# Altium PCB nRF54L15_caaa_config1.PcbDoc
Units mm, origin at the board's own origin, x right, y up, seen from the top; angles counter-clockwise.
Board outline 10.87 x 8.27 mm, 8 copper layers (Top Layer, Mid-Layer 1, Mid-Layer 2, Mid-Layer 3, Mid-Layer 4, Mid-Layer 5, Mid-Layer 6, Bottom Layer), stack 1.547 mm thick; 19 components, 47 nets, 85 pads, 110 vias.
Unrouted connection lines stored in the file: 18.
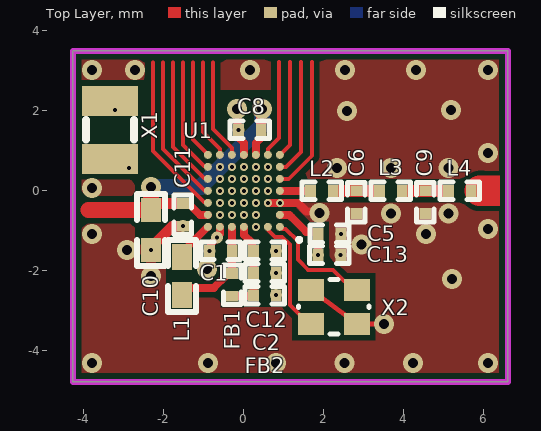
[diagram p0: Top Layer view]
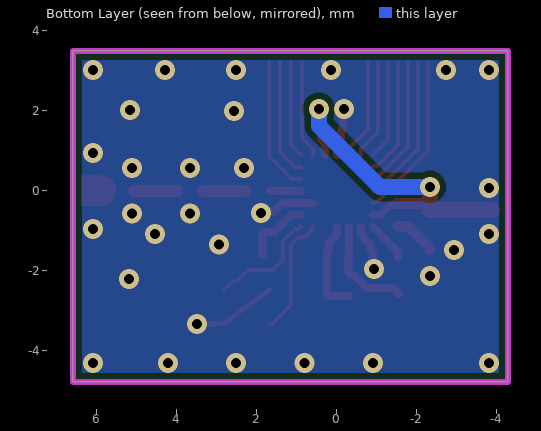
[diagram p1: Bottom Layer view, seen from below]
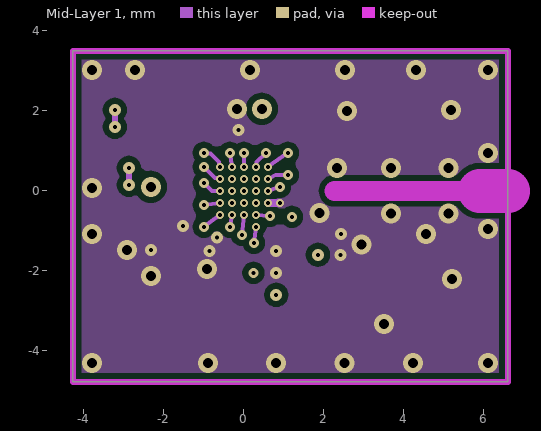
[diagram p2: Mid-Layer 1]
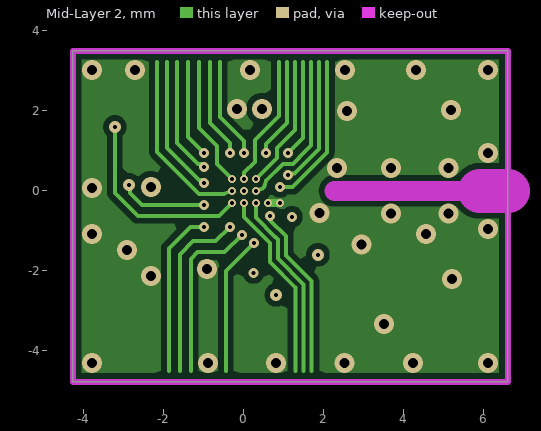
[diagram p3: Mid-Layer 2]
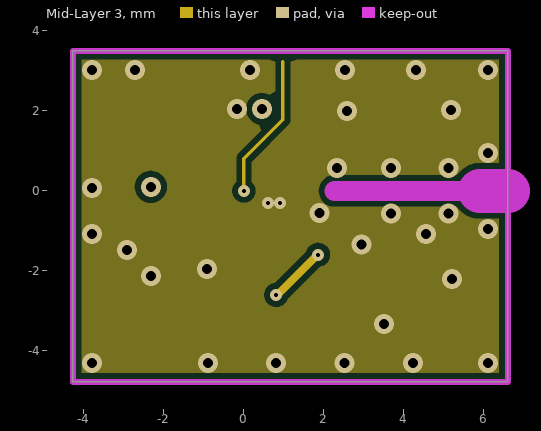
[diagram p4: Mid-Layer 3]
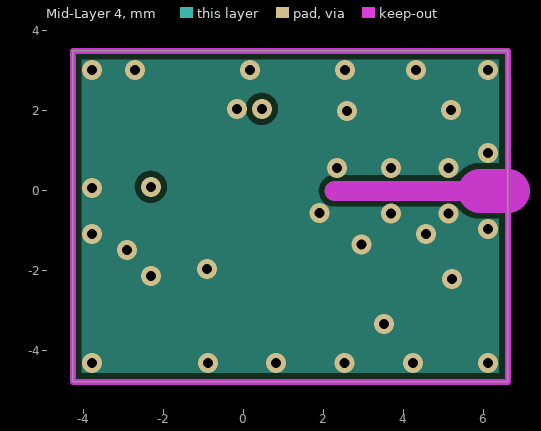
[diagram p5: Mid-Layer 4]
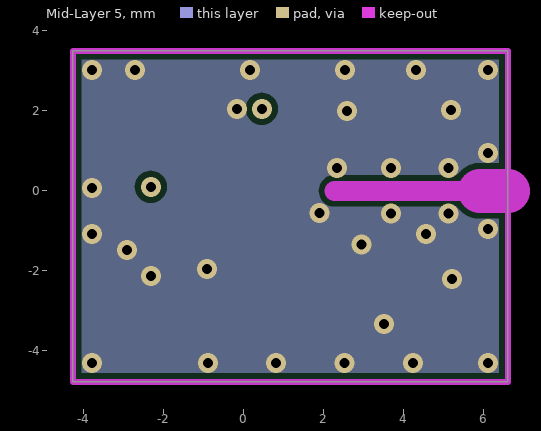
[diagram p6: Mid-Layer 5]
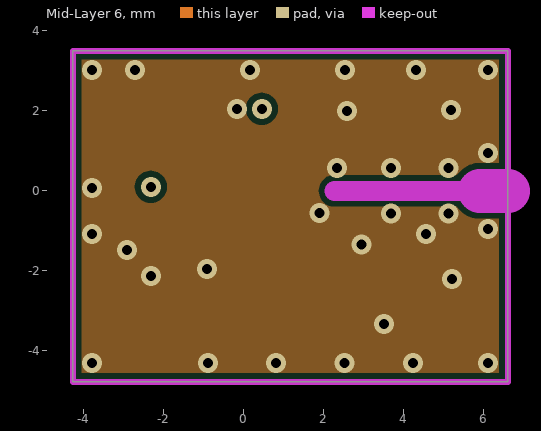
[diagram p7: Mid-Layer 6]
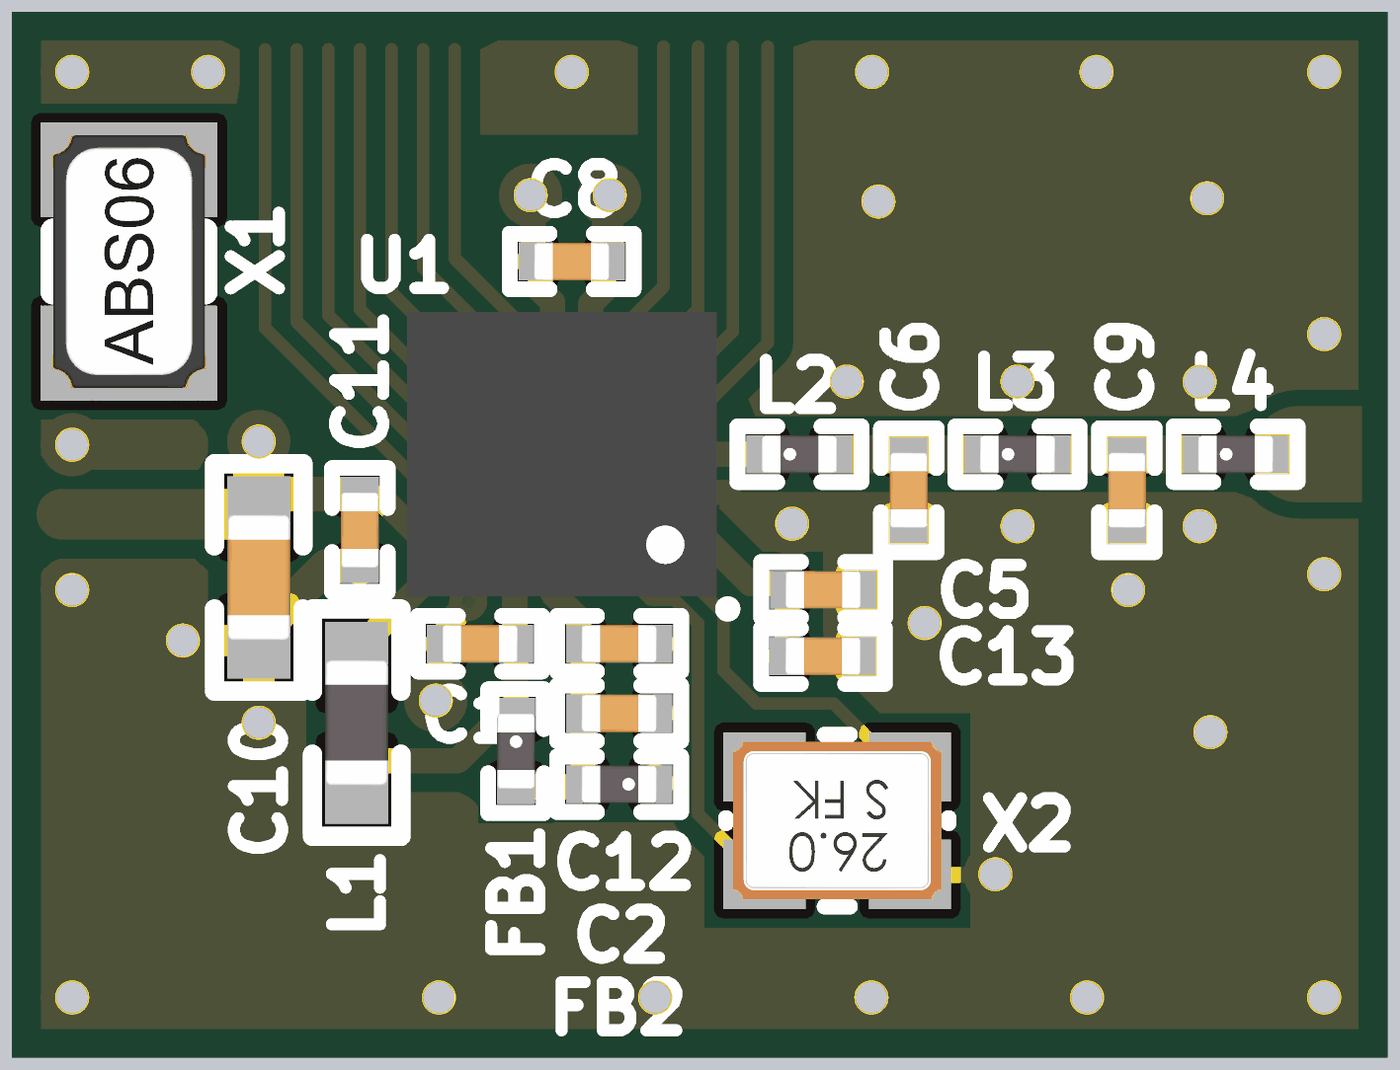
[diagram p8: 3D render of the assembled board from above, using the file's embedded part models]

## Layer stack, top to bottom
Top Solder: solder mask 0.011, Solder Resist, Dk 3.5
Top Layer: signal copper 0.035
Dielectric 1: prepreg 0.08, Dk 4.2
Mid-Layer 1: signal copper 0.035
Dielectric 2: prepreg 0.08, Dk 4.1
Mid-Layer 2: signal copper 0.035
Dielectric 6: prepreg 0.08, Dk 4.1
Mid-Layer 3: signal copper 0.035
Dielectric 3: core 0.7874, Dk 4.6
Mid-Layer 4: signal copper 0.035
Dielectric 7: prepreg 0.08, Dk 4.1
Mid-Layer 5: signal copper 0.035
Dielectric 4: prepreg 0.08, Dk 4.1
Mid-Layer 6: signal copper 0.035
Dielectric 5: prepreg 0.08, Dk 4.2
Bottom Layer: signal copper 0.035
Board Layer Stack Bottom Solder: solder mask 0.011, Solder Resist, Dk 3.5

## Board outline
-4.275,-4.775 6.6,-4.775 6.6,3.5 -4.275,3.5

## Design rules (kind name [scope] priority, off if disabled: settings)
Clearance Polygon_ANT [(InNamedPolygon('GND')) or (InNamedPolygon('Bottom_Layer-GND')) or IsRegion vs InNet('RF')] p1: gap=0.127 ignorepadtopadclearanceinfootprint=FALSE
Clearance Clearance_Poly [IsRegion] p2: gap=0.15 ignorepadtopadclearanceinfootprint=FALSE
Clearance [All] p3: gap=0.1 ignorepadtopadclearanceinfootprint=FALSE
ComponentClearance [All] p1 off: gap=0.254 collisioncheckmode=3 verticalgap=0.254 showdistances=FALSE
FabricationTestPointUsage TestPointUsage [All] p1: valid=0 allowmultiple=FALSE
FabricationTestpoint Testpoint [All] p1: side=3 testpointundercomponent=TRUE minsize=1.016 maxsize=2.54 preferedsize=1.524 minholesize=0 maxholesize=1.016 preferedholesize=0.813 testpointgrid=0.025 allowsidetop=TRUE allowsidebottom=TRUE usegrid=TRUE gridtolerance=0
Height [All] p1 off: minheight=0 maxheight=25.4 prefheight=12.7
HoleSize [All] p1: absolutevalues=TRUE maxlimit=4 minlimit=0.1 maxpercent=80.000 minpercent=20.000
HoleToHoleClearance [IsThruVia vs IsThruVia] p1: gap=0.36 allowstackedmicrovias=TRUE
MinimumAnnularRing [All] p1 off: minimumring=0.152
PlaneClearance [All] p1: clearance=0.2
PolygonConnect "Direct Connect" [isVia and innet(gnd) or InComponent('C6') or InComponent('C9') or InComponent('C3') or  InComponent('C5') or InComponent('C13')] p1: connectstyle=Direct reliefconductorwidth=0.254 reliefentries=4 polygonreliefangle="90 Angle" airgapwidth=0.254
PolygonConnect [All] p2: thpad.connectstyle=Relief thpad.reliefconductorwidth=0.254 thpad.reliefentries=4 thpad.polygonreliefangle="90 Angle" thpad.airgapwidth=0.15 smdpad.connectstyle=Relief smdpad.reliefconductorwidth=0.25 smdpad.reliefentries=4 smdpad.polygonreliefangle="90 Angle" smdpad.airgapwidth=0.15 via.connectstyle=Direct via.reliefconductorwidth=0.254 via.reliefentries=4 via.polygonreliefangle="90 Angle" via.airgapwidth=0.25
RoutingVias [All] p1: holewidth=0.2 width=0.4 viastyle="Through Hole" minholewidth=0.1 minwidth=0.2 maxholewidth=1 maxwidth=2
SilkToSolderMaskClearance SilkscreenOverComponentPads [IsPad] p1: minsilkscreentomaskgap=0.254 clearancetoexposedcopper=TRUE
SolderMaskExpansion SolderMaskExpansion_via [IsVia] p1: expansion=0.102 istentingtop=TRUE
SolderMaskExpansion [All] p2: expansion=0.076 istentingtop=FALSE
Width [All] p1: maxlimit=3 minlimit=0.09 preferedwidth=0.15
22 further rules are at their usual default settings.

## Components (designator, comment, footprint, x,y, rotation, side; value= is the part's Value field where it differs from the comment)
C1 "2.2µF" CAPC0603X03L_C -0.575,-1.5 r0 top
C2 "2.2µF" CAPC0603X03L_C 0.525,-2.05 r180 top
C5 "3.9pF" CAPC0603X03L_C 2.138,-1.073 r180 top
C6 "1.2pF" CAPC0603X03L_C 2.815,-0.285 r90 top
C8 "100nF" CAPC0603X03L_C 0.15,1.525 r180 top
C9 "1.2pF" CAPC0603X03L_C 4.54,-0.285 r90 top
C10 "10µF" CAPC1005X04L -2.325,-0.975 r90 top
C11 "100nF" CAPC0603X03L_C -1.525,-0.6 r270 top
C12 "10nF" CAPC0603X03L_C 0.525,-1.5 r180 top
C13 "2.2µF" CAPC0603X03L_C 2.137,-1.598 r180 top
FB1 "120R/0.2A" INDC0603X03L_C -0.29,-2.35 r270 top
FB2 "120R/0.2A" INDC0603X03L_C 0.525,-2.612 r180 top
L1 "4.7µH" INDC1005X04L -1.55,-2.125 r270 top
L2 "4.7nH" INDC0603X03L_C 1.95,0 r0 top
L3 "4.7nH" INDC0603X03L_C 3.675,0 r0 top
L4 "2.0nH" INDC0603X03L_C 5.4,0 r0 top
U1 "nRF54L15-CAAA" BGA49C30P7x7_2245X2451X48 0.084,0 r180 top locked
X1 "32.768kHz" XTAL_2012 -3.35,1.525 r90 top
X2 "32MHz" BT-XTAL_1612 2.25,-2.9 r180 top

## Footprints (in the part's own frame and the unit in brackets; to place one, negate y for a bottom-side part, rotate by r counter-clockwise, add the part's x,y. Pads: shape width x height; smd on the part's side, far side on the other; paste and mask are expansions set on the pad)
BGA49C30P7x7_2245X2451X48 [mm] "BGA/CSP, 47-Leads, Body 0.42x2.451mmx2.245mm, Pitch 0.30mm"
  round 0.2 smd mask+0.025: A1(-0.816,0.9) A2(-0.516,0.9) A3(-0.216,0.9) A4(0.084,0.9) A5(0.384,0.9) A6(0.684,0.9) A7(0.984,0.9) B1(-0.816,0.6) B3(-0.216,0.6) B4(0.084,0.6) B5(0.384,0.6) B6(0.684,0.6) B7(0.984,0.6) C2(-0.516,0.3) C3(-0.216,0.3) C4(0.084,0.3) C5(0.384,0.3) C6(0.684,0.3) C7(0.984,0.3) D1(-0.816,0) D2(-0.516,0) D3(-0.216,0) D4(0.084,0) D5(0.384,0) D6(0.684,0) D7(0.984,0) E1(-0.816,-0.3) E2(-0.516,-0.3) E3(-0.216,-0.3) E4(0.084,-0.3) E5(0.384,-0.3) E6(0.684,-0.3) E7(0.984,-0.3) F1(-0.816,-0.6) F2(-0.516,-0.6) F3(-0.216,-0.6) F4(0.084,-0.6) F5(0.384,-0.6) F6(0.684,-0.6) F7(0.984,-0.6) G1(-0.816,-0.9) G2(-0.516,-0.9) G3(-0.216,-0.9) G4(0.084,-0.9) G5(0.384,-0.9) G6(0.684,-0.9) G7(0.984,-0.9)
  silkscreen extent -1.35,1.18 -1.25,1.27, body extent -1.21,-1.12 1.24,1.12, height 0.48
BT-XTAL_1612 [mm] "Crystal 1.6 x 1.2 mm"
  rect 0.65x0.55 smd: 1(-0.575,-0.425) 2(0.575,-0.425) 3(0.575,0.425) 4(-0.575,0.425)
  silkscreen extent -0.88,-0.68 0.88,0.68, body extent -0.83,-0.63 0.83,0.63, height 0.41
CAPC0603X03L_C [mm] "Chip Capacitor, 2-Leads, Body 0.6x0.3mm, IPC High Density"
  rect 0.27x0.3 smd mask+0.05: 1(-0.285,0) 2(0.285,0)
  silkscreen extent -0.49,-0.22 0.49,0.22, body extent -0.3,-0.15 0.3,0.15, height 0.3
CAPC1005X04L [mm] "Chip Capacitor, 2-Leads, Body 1.0x0.5mm, IPC High Density"
  rect 0.6x0.5 smd: 1(-0.5,0) 2(0.5,0)
  silkscreen extent -0.9,-0.35 0.9,0.35, body extent -0.5,-0.25 0.5,0.25, height 0.5
INDC0603X03L_C [mm] "Chip Inductor, 2-Leads, Body 0.6x0.3mm, IPC High Density"
  rect 0.27x0.3 smd: 1(-0.285,0) 2(0.285,0)
  silkscreen extent -0.49,-0.22 0.49,0.22, body extent -0.3,-0.15 0.3,0.15, height 0.3
INDC1005X04L [mm] "Chip Inductor, 2-Leads, Body 1.0x0.5mm, IPC High Density"
  rect 0.65x0.5 smd: 1(-0.475,0) 2(0.475,0)
  silkscreen extent -0.9,-0.35 0.9,0.35, body extent -0.5,-0.25 0.5,0.25, height 0.5
XTAL_2012 [mm] "XTAL SMD 2.0 x 1.2 mm"
  rect 0.75x1.4 smd: 1(-0.725,0) 2(0.725,0)
  silkscreen extent -0.24,-0.6 0.24,0.6, body extent -1,-0.61 1,0.61, height 0.6

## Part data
C1 C2 C13: library part C0201-2µ2-2.5V-X6T-GRM033D80E225ME47D, "Capacitor, Ceramic, 2.2µF 2.5V X6T 0201,±20%", Manufacturer=Murata, Manufacturer Part Number=GRM033R61A225KE47, Part number IPS=N.A., Part number NEMS=100200527, Supplier Part Number 1=81-GRM033D80E225ME7D
C5: library part C0201-3.9p-HQ-Murata, "Capacitor, NP0, ±0.05pF, 25V", Manufacturer=Murata, Manufacturer Part Number=GJM0333C1E3R9WB01, Part number IPS=N.A., Part number NEMS=100200424
C6 C9: library part C0201-1.2p-HQ-Murata, "Capacitor, NP0, ±0.05pF, 50V", Manufacturer=Murata, Manufacturer Part Number=GJM0335C1H1R2WB01D, Part number IPS=N.A., Part number NEMS=100200457, Supplier Part Number 1=490-GJM0335C1H1R2WB01DCT-ND
C8 C11: library part C0201-100n-10V-X7R, "Capacitor, X7R, ±10%", Manufacturer=N.A., Part number NEMS=100200469
C10: library part C0402-10µF-6.3V-X6S, "Capacitor, X6S, ±20%, 6.3V", Manufacturer=N.A., Part number NEMS=100200478
C12: library part C0201-10n-6.3V-X7R, "Capacitor, X7R, 6.3V", Manufacturer=Murata, Manufacturer Part Number=GRM033R70J103KA01D, Part number IPS=N.A., Part number NEMS=100200407, Supplier Part Number 1=490-1262-1-ND
FB1 FB2: library part FB0201-120R@100M-200mA-BLM03AG121SN1D, "Ferrite Bead, 120 Ohm @ 100MHz, 200mA, 500 mOhm Max", Manufacturer=Murata, Manufacturer Part Number=BLM03AG121SN1D, Part number IPS=N.A., Part number NEMS=100300419, Supplier Part Number 1=490-5622-1-ND
L1: library part L0402-4µ7-PLEA67BCA4R7M-1PT00, "Inductor, 300mA, ±20%, 1.08R", Manufacturer="TDK Corporation", Manufacturer Part Number=PLEA67BCA4R7M-1PT00, Part number IPS=N.A., Part number NEMS=100300441, Supplier Part Number 1=445-PLEA67BCA4R7M-1PT00TR-ND
L2 L3: library part L0201-4n7-HQ-Murata, "Inductor, 400mA, ±3%, 250mOhm", Manufacturer=Murata, Manufacturer Part Number=LQP03HQ4N7H02, Part number IPS=N.A., Part number NEMS=100300231, Supplier Part Number 1=490-13943-1-ND
L4: library part L0201-2n0-HQ-Murata, "Inductor, 600mA, ±0.1ｎH, 120mOhm", Manufacturer=Murata, Manufacturer Part Number=LQP03HQ2N0B02, Part number IPS=00000001670, Part number NEMS=100300207, Part number Norautron=N.A., Supplier Part Number 1=490-13895-1-ND
U1: "Multi-protocol Bluetooth Low Energy, IEEE 802.15.4, ANT and 2.4GHz proprietary Wireless MCU", Manufacturer="Nordic Semiconductor", Part number IPS=N.A., Part number NEMS=102000283
X1: library part XTAL_SMD2012_32.768kHz_9pF_TXC, "XTAL SMD 2012, 32.768kHz, 9pF, ±20ppm", Manufacturer="TXC Corporation", Manufacturer Part Number=9HT11-32.768KDZC-T, Part number IPS=N.A., Part number NEMS=101600107, Supplier Part Number 1=887-1426-2-ND
X2: library part XTAL_SMD1612_32MHz_8pF_Kyocera, "XTAL SMD 1612, 32MHz, Cl=8pF, Tot: ±40ppm, Aging: ±1ppm/year", Manufacturer=Kyocera, Manufacturer Part Number=CX1612DB32000D0WZRC3, Part number IPS=N.A., Part number NEMS=101600029

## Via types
v1: diameter 0.5, hole 0.25, Top Layer to Bottom Layer, tented both sides, 34 vias
v2: diameter 0.2, hole 0.1, Top Layer to Mid-Layer 1, tented top, 26 vias
v3: diameter 0.25, hole 0.1, Mid-Layer 1 to Mid-Layer 2, tented top, 19 vias
v4: diameter 0.3, hole 0.1, Top Layer to Mid-Layer 1, tented top, 13 vias
v5: diameter 0.2, hole 0.1, Mid-Layer 1 to Mid-Layer 2, tented top, 11 vias
v6: diameter 0.2/0.3 (per signal layer), hole 0.1, Mid-Layer 2 to Mid-Layer 3, tented top, 3 vias
v7: diameter 0.3, hole 0.1, Mid-Layer 2 to Mid-Layer 3, tented top, 2 vias
v8: diameter 0.3, hole 0.1, Mid-Layer 1 to Mid-Layer 2, 2 vias

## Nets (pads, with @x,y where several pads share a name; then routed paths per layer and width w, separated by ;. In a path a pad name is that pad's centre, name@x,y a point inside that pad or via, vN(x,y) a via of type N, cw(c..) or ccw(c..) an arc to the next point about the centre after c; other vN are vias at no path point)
DCC: L1.1 U1.A7 | length 1
  Top Layer w0.2: L1.1@-1.525,-1.65 -1.525,-1.525 U1.A7
DECA: C2.2 C12.2 FB1.2 FB2.2 U1.A4 | length 2.4
  Top Layer w0.2: FB1.2 0.205,-2.635 0.24,-2.6 v3(0.24,-2.05) ; U1.A4 0,-1.1 0.205,-1.305 0.205,-1.515 0.24,-1.55 v3(0.24,-2.05) ; C2.2@0.275,-2.085 v3(0.24,-2.05)
  other v3: 1.2,-0.65
DECD: C1.2 FB1.1 L1.2 U1.A5 | length 2.6
  Top Layer w0.2: L1.2@-1.55,-2.575 -1.4,-2.425 -0.75,-2.425 -0.425,-2.1 -0.34,-2.1 -0.298,-2.058 -0.298,-2.038 -0.29,-2.03 C1.2@-0.29,-1.515 ; U1.A5 -0.3,-1.49 C1.2
DECRF: C5.2 C13.2 FB2.1 U1.B1 | length 3.5
  Top Layer w0.2: 1.2,-0.664 1.136,-0.6 ; v4(1.852,-1.598) 1.853,-1.058 1.818,-1.023 1.56,-1.023 1.137,-0.6 ; 1.137,-0.6 U1.B1 1.136,-0.6
  Mid-Layer 3 w0.2: v7@0.813,-2.612 0.825,-2.612 1.84,-1.598 v4(1.852,-1.598)
  other v3: 0.81,-2.6 1.852,-1.598
  other v4: 0.81,-2.6
  other v7: 0.81,-2.6 1.852,-1.598
GND: C1.1 C2.1 C5.1 C6.1 C8.2 C9.1 C10.1 C11.2 C12.1 C13.1 U1.A6 U1.C2 U1.G4 X2.2 X2.4 | length 7.4
  Top Layer w0.127: X2.2@1.68,-2.47 1.942,-2.663 2.569,-3.127 2.83,-3.32 3.092,-3.33 3.495,-3.33 v1@3.505,-3.32
  Top Layer w0.2: v1(-0.925,-1.95) -0.892,-1.917 -0.892,-1.537 -0.825,-1.47 -0.825,-1.336 -0.669,-1.18 v4(-0.669,-1.169) ; v4@-0.65,-1.15 v4(-0.669,-1.169) ; U1.A6 -0.6,-1.073 -0.669,-1.142 v4(-0.669,-1.169) ; v1(-0.175,2.05) -0.155,2.03 -0.155,1.545 v4(-0.135,1.525) ; C8.2@-0.115,1.49 -0.1,1.475 -0.1,1.3 0,1.2 U1.G4 ; v5(0.6,-0.3) v6(0.9,-0.3) 1.355,-0.3 1.57,-0.515 v1@1.725,-0.515
  Top Layer w0.27: v4(-2.325,-1.475) -2.325,-1.425 -1.785,-0.885 v4(-1.525,-0.885)
  Mid-Layer 1 w0.2: v5(0.6,-0.3) v6(0.9,-0.3)
  Mid-Layer 2 w0.2: v5(0.6,-0.3) v6(0.9,-0.3)
  other v1: -3.8,-4.3 -0.9,-4.3 0.81,-4.3 2.52,-4.3 4.225,-4.3 6.1,-4.3 3.5,-3.325 5.2,-2.2 -2.325,-2.125 -2.925,-1.475 2.941,-1.336 -3.8,-1.075 4.55,-1.075 6.1,-0.95 3.675,-0.57 5.115,-0.57 1.893,-0.55 -3.8,0.075 2.325,0.575 3.675,0.575 5.115,0.573 6.1,0.95 2.575,2 5.175,2.025 -3.8,3.025 -2.725,3.025 0.15,3.025 2.525,3.025 4.3,3.025 6.1,3.025
  other v2: 0.6,-0.3 0.9,-0.3
  other v4: 0.81,-2.05 2.422,-1.598 -0.86,-1.5 0.81,-1.5 2.423,-1.073
  other v5: 0.9,-0.3
  other v6: 0.6,-0.3
NetC6_2: C6.2 L2.2 L3.1 | length 1.1
  Top Layer w0.3: L2.2@2.275,0 C6.2 L3.1@3.35,0
NetC9_2: C9.2 L3.2 L4.1 | length 1.1
  Top Layer w0.3: L3.2@4,0 C9.2 L4.1@5.075,0
NetL2_1: L2.1 U1.D1 | length 0.8
  Top Layer w0.2: U1.D1 L2.1
NRESET: U1.D2 | length 4.1
  Mid-Layer 1 w0.1: v2(0.6,0) 0.85,0.083 v3(0.9,0.1)
  Mid-Layer 2 w0.1: v3(0.9,0.1) 1.216,0.1 2.075,0.959 2.075,0.975 2.08,0.98 2.08,3.225
P0.00: U1.G1 | length 2.4
  Top Layer w0.1: U1.G1 1.15,1.15 1.15,3.225
P0.01: U1.F1 | length 2.9
  Top Layer w0.1: U1.F1 1.05,0.6 1.425,0.975 1.425,3.225
P0.02: U1.E2 | length 3.7
  Mid-Layer 1 w0.1: v2(0.6,0.3) 0.638,0.319 0.8,0.4 v3(1.1,0.4)
  Mid-Layer 2 w0.1: v3(1.1,0.4) 1.129,0.429 1.262,0.429 1.575,0.742 1.575,0.749 1.875,1.049 1.875,3.225
P0.03: U1.E1 | length 3.4
  Top Layer w0.1: U1.E1 1.122,0.3 1.7,0.878 1.7,3.225
P0.04: U1.D3 | length 4
  Mid-Layer 2 w0.1: v5(0.3,0) 0.47,0.057 0.503,0.09 0.56,0.259 ; 0.56,0.26 0.975,0.675 1.225,0.675 1.375,0.825 1.375,0.831 1.675,1.131 1.675,3.225
  other v2: 0.3,0
P1.00/XL1: U1.C5 X1.2 | length 5.4
  Mid-Layer 1 w0.15: v8(-3.225,1.6) v4(-3.225,2.025)
  Mid-Layer 2 w0.1: v8(-3.225,1.6) -3.225,-0.05 -2.65,-0.625 -0.625,-0.625 v2(-0.3,-0.3)
  other v5: -0.3,-0.3
P1.01/XL2: U1.C6 X1.1 | length 3
  Mid-Layer 1 w0.1: v3@-0.971,-0.321 v3(-1,-0.35) v2(-0.6,-0.3)
  Mid-Layer 1 w0.15: v8(-2.875,0.15) v4(-2.875,0.575)
  Mid-Layer 2 w0.1: v8@-2.85,0.15 -2.85,-0.05 -2.55,-0.35 v3(-1,-0.35)
P1.02/NFC1: U1.C7 | length 4.1
  Top Layer w0.1: -2.275,3.203 -2.275,1 -1,-0.275 -0.939,-0.275 -0.914,-0.3 U1.C7
P1.03/NFC2: U1.D5 | length 4.6
  Mid-Layer 2 w0.1: -2.175,3.225 -2.175,0.975 -1.125,-0.075 -0.5,-0.075 -0.338,-0.014 v5(-0.3,0)
  other v2: -0.3,0
P1.04/AIN0: U1.D6 | length 3.9
  Mid-Layer 1 w0.1: v3(-1,0.2) -0.8,0 v2(-0.6,0)
  Mid-Layer 2 w0.1: -1.925,3.225 -1.925,1.075 -1.125,0.275 v3@-1,0.275 ; v3@-1.041,0.2 v3(-1,0.2)
P1.05/AIN1: U1.E6 | length 3.5
  Mid-Layer 1 w0.1: v3(-1,0.6) -0.719,0.319 -0.619,0.319 v2(-0.6,0.3)
  Mid-Layer 2 w0.1: -1.675,3.225 -1.675,1.2 -1.15,0.675 v3@-1,0.675 ; v3@-1.041,0.6 v3(-1,0.6)
P1.06/AIN2: U1.D7 | length 3.7
  Top Layer w0.1: -2.025,3.203 -2.025,1.05 -0.985,0.01 U1.D7@-0.91,0.01 ; U1.D7@-0.919,0.019 U1.D7
P1.07/AIN3: U1.E7 | length 3.3
  Top Layer w0.1: -1.775,3.203 -1.775,1.1 -0.994,0.319 U1.E7@-0.9,0.319 ; U1.E7@-0.919,0.319 U1.E7
P1.08: U1.F7 | length 2.9
  Top Layer w0.1: -1.525,3.203 -1.525,1.15 -1,0.625 U1.F7@-0.9,0.625
P1.09*: U1.B3 | length 4.7
  Mid-Layer 1 w0.1: v2(0.3,-0.6) v3(0.65,-0.625)
  Mid-Layer 2 w0.1: v3@0.65,-0.625 0.669,-0.644 0.669,-0.75 1.049,-1.13 1.049,-1.614 1.691,-2.257 1.691,-3.2 1.691,-4.5
P1.10*: U1.C3 | length 4.7
  Mid-Layer 2 w0.1: v5(0.3,-0.3) 0.3,-0.667 0.784,-1.151 0.787,-1.151 0.849,-1.213 0.849,-1.697 1.491,-2.34 1.491,-4.5
  other v2: 0.3,-0.3
P1.11*: U1.C4 | length 4.7
  Mid-Layer 2 w0.1: v5(0,-0.3) 0,-0.65 0.649,-1.299 0.649,-1.78 1.291,-2.422 1.291,-4.5
  other v2: 0,-0.3
P1.12*: U1.A3 | length 3.9
  Mid-Layer 1 w0.1: v3(0.25,-1.3) v2(0.3,-0.9)
  Mid-Layer 2 w0.1: -0.45,-4.5 -0.45,-2 v3(0.25,-1.3)
P1.13: U1.B4 | length 4.8
  Mid-Layer 1 w0.1: v3(-0.05,-1.1) v2(0,-0.6)
  Mid-Layer 2 w0.1: -1.325,-4.5 -1.325,-1.7 -1.158,-1.533 -0.483,-1.533 v3(-0.05,-1.1)
P1.14: U1.B5 | length 4.8
  Mid-Layer 1 w0.1: v3(-0.35,-0.9) v2(-0.3,-0.6)
  Mid-Layer 2 w0.1: -1.6,-4.5 -1.6,-1.586 -1.272,-1.258 -0.708,-1.258 v3(-0.35,-0.9)
P1.15: U1.B6 | length 4.7
  Mid-Layer 1 w0.1: v3(-1,-0.9) -0.626,-0.619 v2(-0.6,-0.6)
  Mid-Layer 2 w0.1: -1.875,-4.5 -1.875,-1.439 -1.336,-0.9 v3(-1,-0.9)
P2.00: U1.G6 | length 2.5
  Top Layer w0.1: -1.025,3.203 -1.025,1.475 -0.602,1.052 -0.602,0.902 U1.G6
P2.01: U1.G7 | length 2.5
  Top Layer w0.1: -1.275,3.203 -1.275,1.284 -0.9,0.909 U1.G7
P2.02: U1.F6 | length 3
  Mid-Layer 1 w0.1: v3(-1,0.95) -0.981,0.931 -0.831,0.931 -0.619,0.719 -0.619,0.619 v2(-0.6,0.6)
  Mid-Layer 2 w0.1: -1.4,3.225 -1.4,1.35 v3(-1,0.95)
P2.03: U1.E5 | length 3.3
  Mid-Layer 2 w0.1: -1.125,3.225 -1.125,1.575 -0.675,1.125 -0.675,0.675 v5@-0.302,0.302
  other v2: -0.3,0.3
  other v5: -0.3,0.3
P2.04: U1.F5 | length 2.8
  Mid-Layer 1 w0.1: v3(-0.35,0.95) v2(-0.3,0.6)
  Mid-Layer 2 w0.1: -0.85,3.225 -0.85,1.7 -0.35,1.2 v3(-0.35,0.95)
P2.05: U1.G5 | length 2.5
  Top Layer w0.1: -0.775,3.203 -0.775,1.55 -0.301,1.076 U1.G5@-0.301,0.901
P2.06: U1.F4 | length 2.9
  Mid-Layer 1 w0.1: v2(0,0.6) v3(0,0.95)
  Mid-Layer 2 w0.1: -0.6,3.225 -0.6,1.85 0,1.25 v3(0,0.95)
P2.07: U1.E4 | length 3.3
  Mid-Layer 2 w0.1: v5(0,0.3) 0.004,0.304 0.004,0.454 0.275,0.725 0.275,1.275 0.875,1.875 0.875,3.225
  other v2: 0,0.3
P2.08: U1.D4 | length 3.6
  Mid-Layer 3 w0.09: v6(0,0) 0,0.8 0.975,1.775 0.975,3.229
  other v2: 0,0
  other v5: 0,0
P2.09: U1.F3 | length 2.9
  Mid-Layer 1 w0.1: v2(0.3,0.6) 0.319,0.619 0.319,0.719 v3(0.55,0.95)
  Mid-Layer 2 w0.1: v3(0.55,0.95) 0.55,1.175 1.075,1.7 1.075,3.225
P2.10: U1.G2 | length 2.4
  Top Layer w0.1: U1.G2 0.602,0.902 0.602,1.052 0.875,1.325 0.875,3.225
RF: L4.2 | length 0.1
  Top Layer w0.762: 5.9,0 6.01,0
SWDCLK: U1.E3 | length 3.3
  Mid-Layer 2 w0.1: v2(0.3,0.3) 0.825,0.825 0.825,1.075 1.275,1.525 1.275,3.225
  other v5: 0.3,0.3
SWDIO: U1.F2 | length 3
  Mid-Layer 1 w0.1: v2(0.6,0.6) 0.603,0.602 v3(1.1,0.95)
  Mid-Layer 2 w0.1: v3(1.1,0.95) 1.475,1.325 1.475,3.225
VDD_nRF: C8.1 C10.2 C11.1 U1.B7 U1.G3 | length 8.5
  Top Layer w0.2: C11.1@-1.49,-0.35 -1.35,-0.35 -1.1,-0.6 U1.B7 ; U1.G3 0.3,1.192 0.4,1.292 C8.1@0.4,1.525 ; C8.1 C8.1@0.444,1.534 ; v1@0.444,2.044 v1(0.45,2.05)
  Top Layer w0.25: C8.1 v1@0.435,2.035
  Top Layer w0.27: C10.2@-2.165,-0.315 C11.1
  Top Layer w0.4: -3.881,-0.475 C10.2 v1(-2.325,0.1)
  Bottom Layer w0.4: v1(-2.325,0.1) -1.075,0.1 0.45,1.625 v1(0.45,2.05)
XC1: U1.A1 X2.1 | length 2.8
  Top Layer w0.1: U1.A1 0.927,-0.9 0.977,-0.95 1.042,-0.95 1.35,-1.258 1.35,-1.714 1.61,-1.974 2.224,-1.974 2.5,-2.25 2.6,-2.25 X2.1
XC2: U1.A2 X2.3 | length 3
  Top Layer w0.1: U1.A2 0.619,-0.919 0.619,-0.994 0.775,-1.15 0.959,-1.15 1.15,-1.341 1.15,-2.85 1.625,-3.325 X2.3

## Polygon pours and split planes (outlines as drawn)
GND on Bottom Layer "GND" (solid, pour order 2): -4.275,3.505 6.6,3.505 6.6,-4.775 -4.275,-4.775
GND on Mid-Layer 4 "GND" (solid, pour order 6): -4.275,-4.775 -4.275,3.5 6.6,3.5 6.6,-4.775
GND on Mid-Layer 5 "GND" (solid, pour order 7): -4.275,-4.775 -4.275,3.5 6.6,3.5 6.6,-4.775
GND on Mid-Layer 6 "GND" (solid, pour order 8): -4.275,-4.775 -4.275,3.5 6.6,3.5 6.6,-4.775
GND on Mid-Layer 1 "GND" (solid, pour order 3): -4.275,3.505 -4.275,-4.775 6.6,-4.775 6.6,3.505 2.464,3.505
GND on Mid-Layer 3 "GND" (solid, pour order 5): -4.275,-4.775 -4.275,3.5 6.6,3.5 6.6,-4.775
GND on Mid-Layer 2 "GND" (solid, pour order 4): -4.275,-4.775 -4.275,3.5 6.6,3.5 6.6,-4.775
GND on Top Layer "GND" (solid, remove dead copper, pour order 1): -4.275,3.505 -4.275,-4.775 6.6,-4.775 6.6,3.505 3.556,3.505

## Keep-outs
Mid-Layer 1:
  lines w0.5: 2.266,0 5.826,0
  lines w1.1: 5.9,0 6.6,0
Mid-Layer 2:
  lines w0.5: 2.266,0 5.826,0
  lines w1.1: 5.9,0 6.6,0
Mid-Layer 6:
  lines w0.5: 2.266,0 5.826,0
  lines w1.1: 5.9,0 6.6,0
Mid-Layer 5:
  lines w0.5: 2.266,0 5.826,0
  lines w1.1: 5.9,0 6.6,0
Mid-Layer 3:
  lines w0.5: 2.266,0 5.826,0
  lines w1.1: 5.9,0 6.6,0
Mid-Layer 4:
  lines w0.5: 2.266,0 5.826,0
  lines w1.1: 5.9,0 6.6,0
Keep-Out Layer:
  the board outline again, w0.152

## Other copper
Top Layer:
  rectangle net RF: 5.95,-0.381 6.4,0.381
  pour cut-out: 0.674,2.363 -0.6,2.363 -0.6,2.53 0.674,2.53
  pour cut-out: 0.6,0 1.122,0 1.122,-0.6 0.6,-0.6
  pour cut-out: 1.2,-3.75 3.3,-3.75 3.3,-2.05 1.2,-2.05

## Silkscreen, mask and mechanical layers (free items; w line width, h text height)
Mechanical 1:
  the board outline again, w0.152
